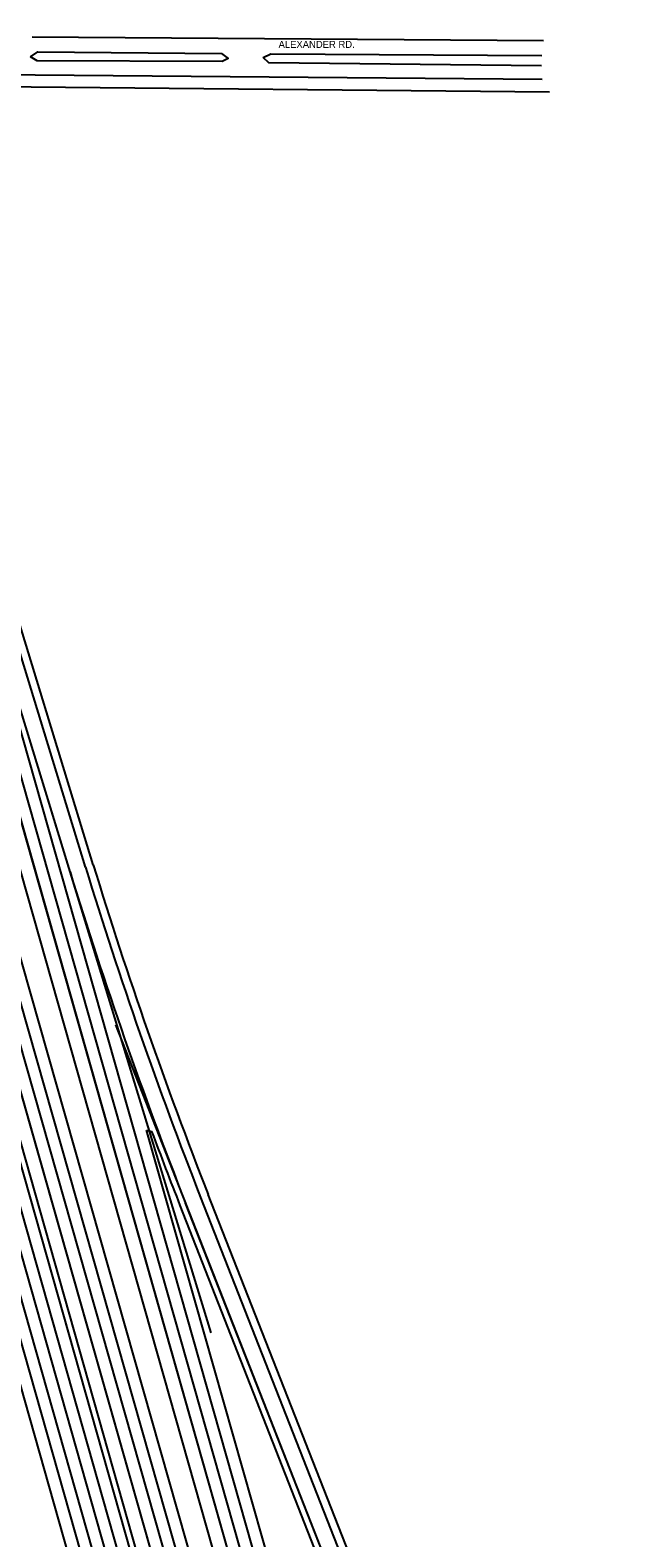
# Model space of a CAD drawing. Extents: x 227157 to 233208, y 434992 to 456232.
# Drawn here: x 229152 to 229741, y 438748 to 440241 of the extents above; entities that cross this region are included whole.
import ezdxf

# ---------------------------------------------------------------- set-up
doc = ezdxf.new("R2010")
doc.units = 0
for name, color, linetype in [('GE_X_Alignment', 7, 'Continuous'), ('PM_X_Edge_Line', 7, 'Continuous'), ('PM_X_Lane_Line', 7, 'Continuous'), ('PV_X_Curb', 7, 'Continuous'), ('PV_X_EOP', 7, 'Continuous'), ('SV_X_Text_Name', 7, 'Continuous')]:
    doc.layers.add(name, color=color, linetype=linetype)

msp = doc.modelspace()

# ---------------------------------------------------------------- linework, layer by layer
at = {"layer": 'GE_X_Alignment'}
for p, q in [((229741.1, 437351.7), (227977.9, 443563.5)), ((229633.3, 437464.5), (227927.6, 443466.1)), ((229609.5, 437429.5), (227988.9, 443142.3)), ((229331.5, 438951.2), (229048.9, 439874.6)), ((229730.5, 437998.1), (229236.9, 439256.1))]:
    msp.add_line(p, q, dxfattribs=at)
for centre, radius, start, end in [((233513.7, 440730.2), 4519.8, 197.0147, 201.422), ((232609.7, 439582.5), 3780.4, 185.6268, 204.1773)]:
    msp.add_arc(centre, radius, start, end, dxfattribs=at)
at = {"layer": 'PM_X_Edge_Line'}
for p, q in [((229405.2, 438534.9), (228394.3, 442096.5)), ((229504.8, 437916.6), (228327.5, 442058.8)), ((229527.9, 437923.2), (228350.6, 442065.3)), ((228263.8, 442041.2), (229294, 438409.6)), ((229328.7, 438419.5), (228298.5, 442051)), ((229191.8, 439407.6), (229048.9, 439874.6)), ((229207.1, 439412.3), (229064.2, 439879.2)), ((229428.3, 438541.5), (229064.3, 439824.1)), ((229529, 438555.4), (229321.1, 439085.3)), ((229514.1, 438549.5), (229306.2, 439079.4))]:
    msp.add_line(p, q, dxfattribs=at)
for centre, radius, start, end in [((233513.7, 440730.2), 4503.8, 197.0147, 201.422), ((233513.7, 440730.2), 4519.8, 197.0147, 201.422), ((232609.7, 439582.5), 3780.4, 185.6268, 204.1773), ((232609.7, 439582.5), 3764.4, 185.6268, 204.1773)]:
    msp.add_arc(centre, radius, start, end, dxfattribs=at)
at = {"layer": 'PM_X_Lane_Line'}
for p, q in [((229416.8, 438538.2), (228405.8, 442099.8)), ((228339.1, 442062.1), (229516.3, 437919.9)), ((229305.6, 438412.9), (228275.4, 442044.5)), ((228286.9, 442047.7), (229317.1, 438416.2)), ((229154.3, 440235), (229660.4, 440231.3)), ((229659.1, 440192.6), (228485.1, 440202.5))]:
    msp.add_line(p, q, dxfattribs=at)
at = {"layer": 'PV_X_Curb'}
msp.add_lwpolyline([(229152.7, 440215.1), (229159.7, 440220), (229341.8, 440218.2), (229348.3, 440213.5), (229342.5, 440210.5), (229159.2, 440211.2)], close=True, dxfattribs=at)
for points in [[(229382.8, 440214.4), (229390.7, 440217.9), (229658.9, 440216.5)], [(229658.7, 440206.3), (229388.6, 440209.1), (229382.8, 440214.4)]]:
    msp.add_lwpolyline(points, dxfattribs=at)
at = {"layer": 'PV_X_EOP'}
for p, q in [((229391.8, 438531.1), (228380.8, 442092.7)), ((229539.4, 437926.5), (228362.2, 442068.6)), ((229340.2, 438422.7), (228310, 442054.3)), ((229391.7, 438263.5), (228314.1, 442054.9)), ((229282.5, 438406.4), (228252.3, 442037.9)), ((228488.6, 440191.8), (229666.6, 440180.4)), ((229214.7, 439414.7), (229071.9, 439881.6)), ((229439.9, 438544.7), (229267.5, 439151.8)), ((229267.5, 439151.8), (229272.6, 439150.6)), ((229536.4, 438558.3), (229328.5, 439088.2)), ((229508.5, 438547.4), (229300.6, 439077.2))]:
    msp.add_line(p, q, dxfattribs=at)
for centre, radius, start, end in [((233513.7, 440730.2), 4495.8, 197.0147, 201.422), ((232609.7, 439582.5), 3758.4, 185.6268, 204.1773), ((233513.7, 440730.2), 4525.8, 200.4274, 201.422)]:
    msp.add_arc(centre, radius, start, end, dxfattribs=at)

# ---------------------------------------------------------------- texts
at = {"layer": 'SV_X_Text_Name'}
msp.add_text('ALEXANDER RD.', height=7, dxfattribs=at).set_placement((229398.2, 440223.9))

doc.saveas('drawing.dxf')
